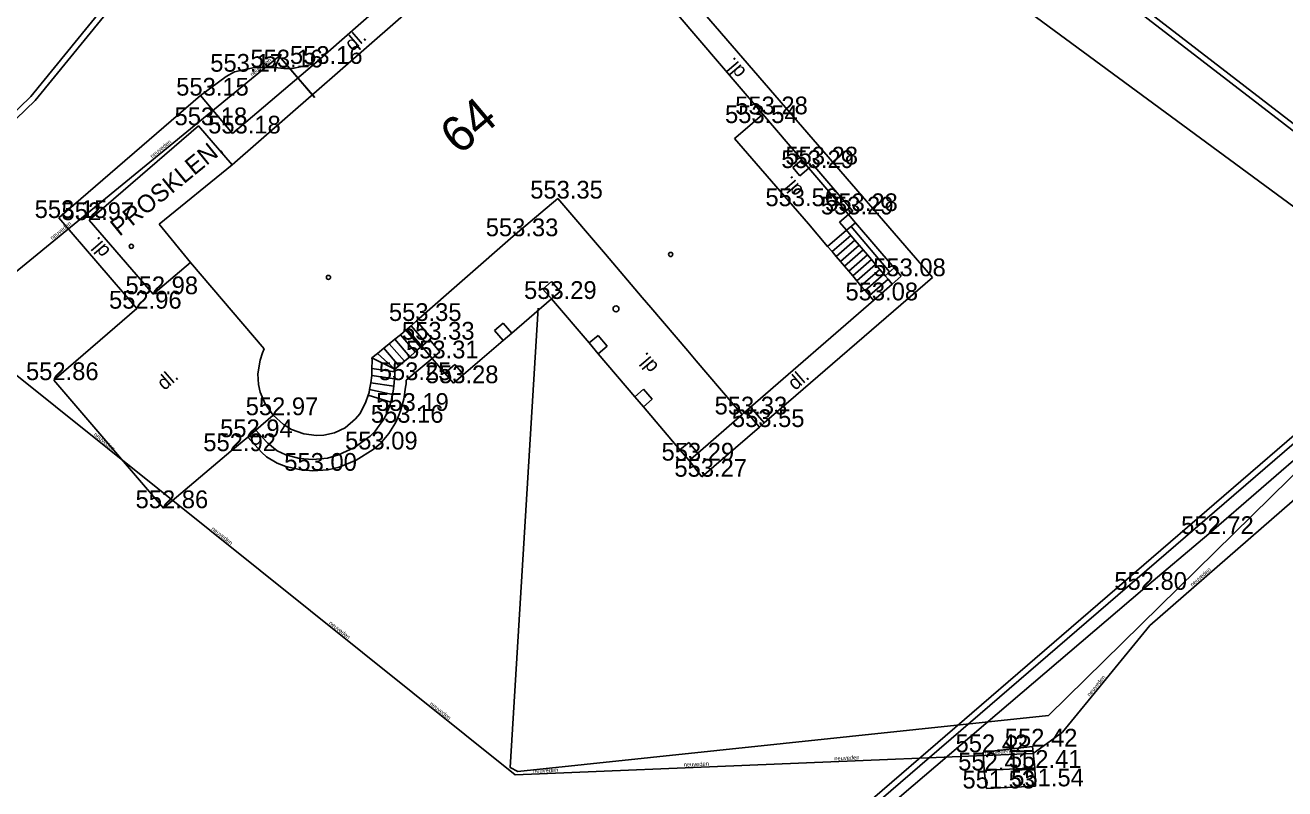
# Model space of a CAD drawing. Extents: x -669995 to -669686, y -1125551 to -1125263.
# Drawn here: x -669941 to -669887.8, y -1125457 to -1125424.8 of the extents above; entities that cross this region are included whole.
import ezdxf

# ---------------------------------------------------------------- set-up
doc = ezdxf.new("R2010")
doc.units = 0
for name, color, linetype in [('G_Bod_tecka', 7, 'Continuous'), ('G_Bod_vyska', 7, 'Continuous'), ('G_Budovy-znacky', 7, 'Continuous'), ('G_Budovy_Objekty', 7, 'Continuous'), ('G_Budovy_vstupy', 7, 'Continuous'), ('G_Cesty_Schody', 7, 'Continuous'), ('G_Cisla_popisna', 7, 'Continuous'), ('G_Plochy_zpevnene', 7, 'Continuous'), ('G_Ploty', 7, 'Continuous'), ('G_Popisy_povrchu', 7, 'Continuous'), ('G_Poznamky_odkaz', 7, 'Continuous'), ('G_Z_KANAL_podz_kotovane', 7, 'Continuous'), ('G_Z_SPOJE_podz_geodeticky', 7, 'Continuous'), ('G_Z_SPOJE_podz_kotovane', 7, 'Continuous'), ('G_Z_SPOJE_podz_priblizne', 7, 'Continuous'), ('G_Zabradli_Svodidla', 7, 'Continuous'), ('Vrstva 13', 7, 'Continuous'), ('Vrstva 3', 7, 'Continuous')]:
    doc.layers.add(name, color=color, linetype=linetype)

msp = doc.modelspace()

# ---------------------------------------------------------------- linework, layer by layer
at = {"layer": 'G_Bod_tecka'}
for p, q in [((-669930.42, -1125426.54), (-669930.42, -1125426.54)), ((-669928.75, -1125426.39), (-669928.75, -1125426.39)), ((-669932.13, -1125426.72), (-669932.13, -1125426.72)), ((-669933.57, -1125427.73), (-669933.57, -1125427.73)), ((-669909.81, -1125428.52), (-669909.81, -1125428.52)), ((-669933.64, -1125428.98), (-669933.64, -1125428.98)), ((-669910.24, -1125428.89), (-669910.24, -1125428.89)), ((-669932.22, -1125429.33), (-669932.22, -1125429.33)), ((-669907.86, -1125430.79), (-669907.86, -1125430.79)), ((-669907.69, -1125430.64), (-669907.69, -1125430.64)), ((-669918.47, -1125432.08), (-669918.47, -1125432.08)), ((-669908.52, -1125432.4), (-669908.52, -1125432.4)), ((-669939.55, -1125432.9), (-669939.55, -1125432.9)), ((-669938.27, -1125432.99), (-669938.27, -1125432.99)), ((-669906.19, -1125432.75), (-669906.19, -1125432.75)), ((-669906.01, -1125432.61), (-669906.01, -1125432.61)), ((-669920.35, -1125433.67), (-669920.35, -1125433.67)), ((-669903.96, -1125435.36), (-669903.96, -1125435.36)), ((-669935.57, -1125436.12), (-669935.57, -1125436.12)), ((-669918.73, -1125436.32), (-669918.73, -1125436.32)), ((-669905.13, -1125436.38), (-669905.13, -1125436.38)), ((-669936.25, -1125436.73), (-669936.25, -1125436.73)), ((-669924.44, -1125437.25), (-669924.44, -1125437.25)), ((-669923.89, -1125438.04), (-669923.89, -1125438.04)), ((-669923.78, -1125438.83), (-669923.78, -1125438.83)), ((-669939.76, -1125439.75), (-669939.76, -1125439.75)), ((-669924.87, -1125439.75), (-669924.87, -1125439.75)), ((-669922.88, -1125439.88), (-669922.88, -1125439.88)), ((-669930.49, -1125441.23), (-669930.49, -1125441.23)), ((-669925.12, -1125441.05), (-669925.12, -1125441.05)), ((-669910.68, -1125441.2), (-669910.68, -1125441.2)), ((-669925.33, -1125441.55), (-669925.33, -1125441.55)), ((-669909.95, -1125441.73), (-669909.95, -1125441.73)), ((-669931.57, -1125442.16), (-669931.57, -1125442.16)), ((-669932.28, -1125442.75), (-669932.28, -1125442.75)), ((-669926.27, -1125442.68), (-669926.27, -1125442.68)), ((-669928.82, -1125443.58), (-669928.82, -1125443.58)), ((-669912.92, -1125443.15), (-669912.92, -1125443.15)), ((-669912.38, -1125443.83), (-669912.38, -1125443.83)), ((-669935.13, -1125445.16), (-669935.13, -1125445.16)), ((-669890.97, -1125446.25), (-669890.97, -1125446.25)), ((-669893.77, -1125448.61), (-669893.77, -1125448.61)), ((-669898.42, -1125455.23), (-669898.42, -1125455.23)), ((-669900.5, -1125455.47), (-669900.5, -1125455.47)), ((-669900.45, -1125456.24), (-669900.45, -1125456.24)), ((-669898.31, -1125456.13), (-669898.31, -1125456.13)), ((-669898.29, -1125456.91), (-669898.29, -1125456.91)), ((-669900.35, -1125457), (-669900.35, -1125457))]:
    msp.add_line(p, q, dxfattribs=at)
at = {"layer": 'G_Budovy-znacky'}
for centre, radius in [((-669936.49, -1125434.1), 0.0875), ((-669913.7, -1125434.44), 0.0875), ((-669928.16, -1125435.41), 0.0875), ((-669916.01, -1125436.74), 0.125)]:
    msp.add_circle(centre, radius, dxfattribs=at)
at = {"layer": 'G_Budovy_Objekty'}
for p, q in [((-669921.89, -1125421.62), (-669932.23, -1125430.65)), ((-669913.39, -1125424.33), (-669909.81, -1125428.52)), ((-669909.81, -1125428.52), (-669910.24, -1125428.89)), ((-669909.81, -1125428.52), (-669908.16, -1125430.44)), ((-669933.65, -1125429.01), (-669938.27, -1125432.99)), ((-669932.23, -1125430.65), (-669933.65, -1125429.01)), ((-669910.95, -1125429.5), (-669911, -1125429.54)), ((-669911, -1125429.54), (-669908.52, -1125432.4)), ((-669932.23, -1125430.65), (-669935.31, -1125433.16)), ((-669908.54, -1125430.76), (-669908.16, -1125430.44)), ((-669908.54, -1125430.76), (-669908.24, -1125431.12)), ((-669908.24, -1125431.12), (-669907.86, -1125430.79)), ((-669908.16, -1125430.44), (-669907.86, -1125430.79)), ((-669907.86, -1125430.79), (-669906.19, -1125432.75)), ((-669918.47, -1125432.08), (-669916.46, -1125434.43)), ((-669935.57, -1125436.12), (-669938.27, -1125432.99)), ((-669906.57, -1125433.08), (-669906.19, -1125432.75)), ((-669906.19, -1125432.75), (-669905.89, -1125433.1)), ((-669935.31, -1125433.16), (-669933.99, -1125434.78)), ((-669907.88, -1125433.15), (-669907.07, -1125434.11)), ((-669907.07, -1125434.11), (-669906.27, -1125433.42)), ((-669906.57, -1125433.08), (-669906.27, -1125433.42)), ((-669906.27, -1125433.42), (-669905.89, -1125433.1)), ((-669906.27, -1125433.42), (-669906.09, -1125433.64)), ((-669905.89, -1125433.1), (-669904.26, -1125435.01)), ((-669924.44, -1125437.25), (-669920.35, -1125433.67)), ((-669906.09, -1125433.64), (-669905.92, -1125433.84)), ((-669905.92, -1125433.84), (-669905.74, -1125434.05)), ((-669905.74, -1125434.05), (-669905.57, -1125434.25)), ((-669907.07, -1125434.11), (-669906.88, -1125434.32)), ((-669906.88, -1125434.32), (-669906.71, -1125434.53)), ((-669906.71, -1125434.53), (-669906.53, -1125434.74)), ((-669905.57, -1125434.25), (-669905.39, -1125434.46)), ((-669905.39, -1125434.46), (-669905.22, -1125434.66)), ((-669933.99, -1125434.78), (-669935.57, -1125436.12)), ((-669933.99, -1125434.78), (-669930.88, -1125438.43)), ((-669906.53, -1125434.74), (-669906.36, -1125434.94)), ((-669906.36, -1125434.94), (-669906.18, -1125435.15)), ((-669905.22, -1125434.66), (-669905.04, -1125434.87)), ((-669905.04, -1125434.87), (-669904.87, -1125435.08)), ((-669904.87, -1125435.08), (-669904.69, -1125435.28)), ((-669904.64, -1125435.34), (-669904.26, -1125435.01)), ((-669904.26, -1125435.01), (-669903.96, -1125435.36)), ((-669918.73, -1125435.58), (-669919.1, -1125435.9)), ((-669918.37, -1125436.01), (-669918.73, -1125435.58)), ((-669906.18, -1125435.15), (-669906.01, -1125435.35)), ((-669906.01, -1125435.35), (-669905.83, -1125435.56)), ((-669905.83, -1125435.56), (-669905.66, -1125435.76)), ((-669904.69, -1125435.28), (-669904.64, -1125435.34)), ((-669904.64, -1125435.34), (-669904.51, -1125435.49)), ((-669904.51, -1125435.49), (-669904.34, -1125435.69)), ((-669903.96, -1125435.36), (-669904.34, -1125435.69)), ((-669919.1, -1125435.9), (-669918.73, -1125436.32)), ((-669918.37, -1125436.01), (-669918.73, -1125436.32)), ((-669905.66, -1125435.76), (-669905.48, -1125435.97)), ((-669905.48, -1125435.97), (-669905.3, -1125436.17)), ((-669905.3, -1125436.17), (-669905.13, -1125436.38)), ((-669904.34, -1125435.69), (-669905.13, -1125436.38)), ((-669918.73, -1125436.32), (-669920.41, -1125437.76)), ((-669917.15, -1125438.18), (-669918.73, -1125436.32)), ((-669914.9, -1125436.26), (-669914.54, -1125436.68)), ((-669905.13, -1125436.38), (-669910.33, -1125440.89)), ((-669924.67, -1125437.45), (-669924.44, -1125437.25)), ((-669924.89, -1125437.64), (-669925.12, -1125437.83)), ((-669924.84, -1125437.6), (-669924.89, -1125437.64)), ((-669924.84, -1125437.6), (-669924.67, -1125437.45)), ((-669924.84, -1125437.6), (-669924.22, -1125438.32)), ((-669920.78, -1125437.34), (-669921.14, -1125437.65)), ((-669921.14, -1125437.65), (-669920.78, -1125438.08)), ((-669920.78, -1125437.34), (-669920.41, -1125437.76)), ((-669920.41, -1125437.76), (-669920.78, -1125438.08)), ((-669925.59, -1125438.21), (-669925.82, -1125438.4)), ((-669925.36, -1125438.02), (-669925.59, -1125438.21)), ((-669925.12, -1125437.83), (-669925.36, -1125438.02)), ((-669920.78, -1125438.08), (-669922.46, -1125439.51)), ((-669916.77, -1125437.86), (-669917.15, -1125438.18)), ((-669917.15, -1125438.18), (-669916.76, -1125438.64)), ((-669916.38, -1125438.32), (-669916.77, -1125437.86)), ((-669926.08, -1125438.62), (-669926.32, -1125438.81)), ((-669925.82, -1125438.4), (-669926.08, -1125438.62)), ((-669924.22, -1125438.32), (-669923.78, -1125438.83)), ((-669923.78, -1125438.83), (-669923.24, -1125439.46)), ((-669916.38, -1125438.32), (-669916.76, -1125438.64)), ((-669915.22, -1125440.45), (-669916.76, -1125438.64)), ((-669912.98, -1125438.51), (-669912.62, -1125438.93)), ((-669926.32, -1125439.56), (-669926.32, -1125439.26)), ((-669922.82, -1125439.09), (-669923.24, -1125439.46)), ((-669922.82, -1125439.09), (-669922.46, -1125439.51)), ((-669926.42, -1125440.15), (-669926.37, -1125439.86)), ((-669926.37, -1125439.86), (-669926.32, -1125439.56)), ((-669923.24, -1125439.46), (-669922.88, -1125439.88)), ((-669922.46, -1125439.51), (-669922.88, -1125439.88)), ((-669914.85, -1125440.13), (-669915.22, -1125440.45)), ((-669914.48, -1125440.56), (-669914.85, -1125440.13)), ((-669914.85, -1125440.88), (-669915.22, -1125440.45)), ((-669914.48, -1125440.56), (-669914.85, -1125440.88)), ((-669913.31, -1125442.69), (-669914.85, -1125440.88)), ((-669911.06, -1125440.76), (-669910.68, -1125441.2)), ((-669910.33, -1125440.89), (-669910.52, -1125441.06)), ((-669910.68, -1125441.2), (-669912.55, -1125442.83)), ((-669910.52, -1125441.06), (-669910.68, -1125441.2)), ((-669912.94, -1125442.38), (-669913.31, -1125442.69)), ((-669912.55, -1125442.83), (-669912.94, -1125442.38)), ((-669912.92, -1125443.15), (-669913.31, -1125442.69)), ((-669912.55, -1125442.83), (-669912.92, -1125443.15)), ((-669898.42, -1125455.23), (-669900.5, -1125455.47)), ((-669898.31, -1125456.13), (-669898.42, -1125455.23)), ((-669900.5, -1125455.47), (-669900.45, -1125456.24)), ((-669898.31, -1125456.13), (-669900.45, -1125456.24)), ((-669900.45, -1125456.24), (-669900.35, -1125457)), ((-669898.29, -1125456.91), (-669898.31, -1125456.13)), ((-669900.35, -1125457), (-669898.29, -1125456.91))]:
    msp.add_line(p, q, dxfattribs=at)
for points in [[(-669930.88, -1125438.43), (-669930.95, -1125438.59), (-669931.05, -1125438.91), (-669931.14, -1125439.48), (-669931.12, -1125439.93), (-669931.04, -1125440.26), (-669930.83, -1125440.75), (-669930.49, -1125441.23), (-669930.06, -1125441.63), (-669929.72, -1125441.83), (-669929.2, -1125442.02), (-669928.66, -1125442.09), (-669928.36, -1125442.08), (-669927.9, -1125441.98), (-669927.46, -1125441.76), (-669927.02, -1125441.39), (-669926.84, -1125441.18), (-669926.7, -1125440.94), (-669926.58, -1125440.67), (-669926.48, -1125440.39), (-669926.44, -1125440.27), (-669926.42, -1125440.15)], [(-669926.32, -1125439.26), (-669926.31, -1125438.92), (-669926.32, -1125438.81)]]:
    msp.add_lwpolyline(points, dxfattribs=at)
at = {"layer": 'G_Budovy_vstupy'}
for p, q in [((-669910.95, -1125429.5), (-669910.24, -1125428.89)), ((-669920.35, -1125433.67), (-669918.47, -1125432.08)), ((-669907.88, -1125433.15), (-669908.52, -1125432.4)), ((-669916.46, -1125434.43), (-669914.9, -1125436.26)), ((-669914.54, -1125436.68), (-669912.98, -1125438.51)), ((-669912.62, -1125438.93), (-669911.06, -1125440.76))]:
    msp.add_line(p, q, dxfattribs=at)
at = {"layer": 'G_Cesty_Schody'}
for p, q in [((-669907.69, -1125430.64), (-669907.86, -1125430.79)), ((-669907.69, -1125430.64), (-669906.01, -1125432.61)), ((-669906.01, -1125432.61), (-669906.19, -1125432.75)), ((-669906.09, -1125433.64), (-669906.88, -1125434.32)), ((-669905.92, -1125433.84), (-669906.71, -1125434.53)), ((-669905.74, -1125434.05), (-669906.53, -1125434.74)), ((-669905.57, -1125434.25), (-669906.36, -1125434.94)), ((-669905.39, -1125434.46), (-669906.18, -1125435.15)), ((-669905.22, -1125434.66), (-669906.01, -1125435.35)), ((-669905.04, -1125434.87), (-669905.83, -1125435.56)), ((-669904.87, -1125435.08), (-669905.66, -1125435.76)), ((-669904.69, -1125435.28), (-669905.48, -1125435.97)), ((-669904.51, -1125435.49), (-669905.3, -1125436.17)), ((-669923.81, -1125437.98), (-669924.44, -1125437.25)), ((-669924.27, -1125438.36), (-669924.89, -1125437.64)), ((-669924.04, -1125438.17), (-669924.67, -1125437.45)), ((-669924.95, -1125438.95), (-669925.59, -1125438.21)), ((-669924.72, -1125438.76), (-669925.36, -1125438.02)), ((-669924.5, -1125438.56), (-669925.12, -1125437.83)), ((-669923.81, -1125437.98), (-669923.89, -1125438.04)), ((-669925.35, -1125439.29), (-669926.32, -1125438.81)), ((-669925.35, -1125439.29), (-669926.08, -1125438.62)), ((-669925.18, -1125439.14), (-669925.82, -1125438.4)), ((-669925.35, -1125439.4), (-669926.32, -1125439.26)), ((-669925.4, -1125440), (-669926.37, -1125439.86)), ((-669925.37, -1125439.7), (-669926.32, -1125439.56)), ((-669925.53, -1125440.68), (-669926.48, -1125440.39)), ((-669925.46, -1125440.36), (-669926.42, -1125440.15)), ((-669910.33, -1125440.89), (-669909.75, -1125441.56)), ((-669930.49, -1125441.23), (-669931.23, -1125441.87)), ((-669910.52, -1125441.06), (-669909.95, -1125441.73))]:
    msp.add_line(p, q, dxfattribs=at)
msp.add_lwpolyline([(-669928.75, -1125426.39), (-669929.21, -1125426.48), (-669929.68, -1125426.58), (-669930.05, -1125426.58), (-669930.42, -1125426.54), (-669931.28, -1125426.54), (-669932.13, -1125426.72), (-669932.48, -1125426.92), (-669932.8, -1125427.16), (-669933.19, -1125427.44), (-669933.57, -1125427.73)], dxfattribs=at)
at = {"layer": 'G_Plochy_zpevnene'}
for p, q in [((-669923.74, -1125421.98), (-669928.75, -1125426.39)), ((-669912.72, -1125423.75), (-669902.64, -1125435.41)), ((-669928.75, -1125426.39), (-669932.22, -1125429.33)), ((-669933.57, -1125427.73), (-669939.55, -1125432.9)), ((-669932.22, -1125429.33), (-669933.57, -1125427.73)), ((-669939.55, -1125432.9), (-669936.25, -1125436.73)), ((-669902.64, -1125435.41), (-669909.75, -1125441.56)), ((-669890.97, -1125446.25), (-669878.91, -1125435.78)), ((-669936.25, -1125436.73), (-669939.76, -1125439.75)), ((-669939.76, -1125439.75), (-669935.13, -1125445.16)), ((-669909.95, -1125441.73), (-669912.38, -1125443.83)), ((-669909.75, -1125441.56), (-669909.95, -1125441.73)), ((-669932.28, -1125442.75), (-669931.57, -1125442.16)), ((-669935.13, -1125445.16), (-669932.28, -1125442.75)), ((-669912.38, -1125443.83), (-669912.92, -1125443.15)), ((-669893.77, -1125448.61), (-669890.97, -1125446.25)), ((-669904.51, -1125457.78), (-669893.77, -1125448.61))]:
    msp.add_line(p, q, dxfattribs=at)
at = {"layer": 'G_Ploty'}
for p, q in [((-669940.74, -1125427.77), (-669920.7, -1125403.21)), ((-669940.55, -1125427.93), (-669920.66, -1125403.56)), ((-669879.12, -1125435.3), (-669920.7, -1125403.21)), ((-669920.66, -1125403.56), (-669879.52, -1125435.31)), ((-669940.74, -1125427.77), (-669966.22, -1125452.38)), ((-669965.88, -1125452.4), (-669940.55, -1125427.93)), ((-669879.52, -1125435.31), (-669905.49, -1125457.7)), ((-669905.22, -1125457.8), (-669879.31, -1125435.47)), ((-669924.22, -1125438.32), (-669924.04, -1125438.17)), ((-669924.04, -1125438.17), (-669923.89, -1125438.04)), ((-669923.45, -1125438.55), (-669923.89, -1125438.04)), ((-669924.95, -1125438.95), (-669924.72, -1125438.76)), ((-669924.87, -1125439.75), (-669923.78, -1125438.83)), ((-669924.72, -1125438.76), (-669924.5, -1125438.56)), ((-669924.5, -1125438.56), (-669924.27, -1125438.36)), ((-669924.27, -1125438.36), (-669924.22, -1125438.32)), ((-669923.78, -1125438.83), (-669923.45, -1125438.55)), ((-669925.35, -1125439.29), (-669925.18, -1125439.14)), ((-669925.35, -1125439.4), (-669925.35, -1125439.29)), ((-669925.18, -1125439.14), (-669924.95, -1125438.95)), ((-669925.4, -1125440), (-669925.37, -1125439.7)), ((-669925.53, -1125440.68), (-669925.46, -1125440.36)), ((-669931.57, -1125442.16), (-669931.23, -1125441.87))]:
    msp.add_line(p, q, dxfattribs=at)
for points in [[(-669931.57, -1125442.16), (-669931.27, -1125442.48), (-669930.98, -1125442.8), (-669930.77, -1125442.99), (-669930.32, -1125443.26), (-669929.96, -1125443.4), (-669929.38, -1125443.53), (-669928.82, -1125443.58), (-669928.18, -1125443.54), (-669927.7, -1125443.42), (-669926.99, -1125443.13), (-669926.27, -1125442.68), (-669925.96, -1125442.42), (-669925.61, -1125442.01), (-669925.33, -1125441.55), (-669925.21, -1125441.3), (-669925.12, -1125441.05), (-669924.98, -1125440.55), (-669924.9, -1125440.04), (-669924.88, -1125439.9), (-669924.87, -1125439.75)], [(-669925.37, -1125439.7), (-669925.36, -1125439.6), (-669925.35, -1125439.4)], [(-669925.46, -1125440.36), (-669925.42, -1125440.21), (-669925.4, -1125440)], [(-669931.23, -1125441.87), (-669930.98, -1125442.14), (-669930.72, -1125442.41), (-669930.32, -1125442.73), (-669929.96, -1125442.9), (-669929.38, -1125443.06), (-669928.82, -1125443.1), (-669928.2, -1125443.04), (-669927.74, -1125442.91), (-669927.06, -1125442.59), (-669926.39, -1125442.12), (-669926.18, -1125441.9), (-669926.01, -1125441.66), (-669925.85, -1125441.44), (-669925.72, -1125441.21), (-669925.57, -1125440.82), (-669925.53, -1125440.68)]]:
    msp.add_lwpolyline(points, dxfattribs=at)
at = {"layer": 'G_Z_KANAL_podz_kotovane'}
for points in [[(-669928.74, -1125427.81), (-669930.24, -1125426.07), (-669943.68, -1125437.06), (-669941.82, -1125439.16), (-669920.27, -1125456.43), (-669898.38, -1125455.52)], [(-669898.38, -1125455.52), (-669897.15, -1125454.62), (-669893.45, -1125450.11), (-669885.03, -1125442.78), (-669884.87, -1125442.37)]]:
    msp.add_lwpolyline(points, dxfattribs=at)
at = {"layer": 'G_Z_SPOJE_podz_geodeticky'}
for points in [[(-669882.04, -1125353.23), (-669888.47, -1125362.55), (-669902.63, -1125378.37), (-669910.95, -1125386.95), (-669915.3, -1125391.93), (-669919.2, -1125397.1), (-669925.01, -1125405.29), (-669926.3, -1125407.53), (-669926.15, -1125411.27), (-669924.02, -1125413.38), (-669921.22, -1125413.87), (-669913.82, -1125412.99), (-669911.46, -1125414.56), (-669901.71, -1125421.87), (-669885.88, -1125433.52)], [(-669919.3, -1125436.71), (-669920.48, -1125456.12), (-669920.16, -1125456.28), (-669897.74, -1125453.92), (-669885.22, -1125441.62), (-669884.53, -1125441.6), (-669868.9, -1125450.43)]]:
    msp.add_lwpolyline(points, dxfattribs=at)
at = {"layer": 'G_Z_SPOJE_podz_kotovane'}
msp.add_lwpolyline([(-669919.3, -1125436.71), (-669920.48, -1125456.12), (-669920.16, -1125456.28), (-669897.74, -1125453.92), (-669885.22, -1125441.62), (-669884.53, -1125441.6), (-669868.9, -1125450.43)], dxfattribs=at)
at = {"layer": 'G_Z_SPOJE_podz_priblizne'}
msp.add_lwpolyline([(-669919.3, -1125436.71), (-669920.48, -1125456.12), (-669920.16, -1125456.28), (-669897.74, -1125453.92), (-669885.22, -1125441.62), (-669884.53, -1125441.6), (-669868.9, -1125450.43)], dxfattribs=at)
at = {"layer": 'G_Zabradli_Svodidla'}
msp.add_line((-669906.08, -1125433.26), (-669904.45, -1125435.17), dxfattribs=at)
at = {"layer": 'Vrstva 13'}
for points in [[(-669928.742, -1125427.808), (-669930.244, -1125426.067), (-669943.68, -1125437.06), (-669941.82, -1125439.16), (-669920.27, -1125456.43), (-669898.384, -1125455.525)], [(-669898.384, -1125455.525), (-669897.15, -1125454.62), (-669893.45, -1125450.11), (-669885.03, -1125442.78), (-669884.87, -1125442.37)]]:
    msp.add_lwpolyline(points, dxfattribs=at)

# ---------------------------------------------------------------- texts
at = {"layer": 'G_Bod_vyska'}
for s, p in [('553.17', (-669933.152, -1125426.72)), ('553.16', (-669931.456, -1125426.54)), ('553.16', (-669929.786, -1125426.39)), ('553.15', (-669934.592, -1125427.73)), ('553.54', (-669911.404, -1125428.89)), ('553.28', (-669910.974, -1125428.52)), ('553.18', (-669934.662, -1125428.98)), ('553.18', (-669933.242, -1125429.33)), ('553.29', (-669909.026, -1125430.79)), ('553.28', (-669908.854, -1125430.64)), ('553.35', (-669919.634, -1125432.08)), ('553.56', (-669909.698, -1125432.4)), ('553.28', (-669907.174, -1125432.61)), ('553.15', (-669940.572, -1125432.9)), ('552.97', (-669939.436, -1125432.99)), ('553.29', (-669907.356, -1125432.75)), ('553.33', (-669921.514, -1125433.67)), ('553.08', (-669905.146, -1125435.36)), ('552.98', (-669936.736, -1125436.12)), ('553.29', (-669919.896, -1125436.32)), ('553.08', (-669906.316, -1125436.38)), ('552.96', (-669937.43, -1125436.73)), ('553.35', (-669925.604, -1125437.25)), ('553.33', (-669925.054, -1125438.04)), ('553.31', (-669924.882, -1125438.83)), ('552.86', (-669940.938, -1125439.75)), ('553.25', (-669926.034, -1125439.75)), ('553.28', (-669924.044, -1125439.88)), ('553.19', (-669926.144, -1125441.05)), ('553.33', (-669911.844, -1125441.2)), ('552.97', (-669931.656, -1125441.23)), ('553.16', (-669926.366, -1125441.55)), ('553.55', (-669911.114, -1125441.73)), ('552.94', (-669932.736, -1125442.16)), ('552.92', (-669933.446, -1125442.75)), ('553.09', (-669927.458, -1125442.68)), ('553.29', (-669914.086, -1125443.15)), ('553.00', (-669930.027, -1125443.58)), ('553.27', (-669913.544, -1125443.83)), ('552.86', (-669936.308, -1125445.16)), ('552.72', (-669892.134, -1125446.25)), ('552.80', (-669894.956, -1125448.61)), ('552.42', (-669901.664, -1125455.47)), ('552.42', (-669899.584, -1125455.23)), ('552.41', (-669901.552, -1125456.24)), ('552.41', (-669899.412, -1125456.13)), ('551.53', (-669901.372, -1125457)), ('551.54', (-669899.312, -1125456.91))]:
    msp.add_text(s, height=0.75, dxfattribs=at).set_placement(p)
at = {"layer": 'G_Cisla_popisna'}
msp.add_text('64', height=1.5, rotation=40.2227, dxfattribs=at).set_placement((-669922.63, -1125430.276))
at = {"layer": 'G_Popisy_povrchu'}
for rotation, p in [(40.8166, (-669927.148, -1125425.881)), (130.442, (-669910.493, -1125426.702)), (130.442, (-669908.073, -1125431.712)), (130.442, (-669937.353, -1125434.282)), (130.442, (-669914.193, -1125439.162)), (40.8166, (-669935.088, -1125440.211)), (40.8166, (-669908.438, -1125440.211))]:
    msp.add_text('dl.', height=0.6, rotation=rotation, dxfattribs=at).set_placement(p)
at = {"layer": 'G_Poznamky_odkaz'}
msp.add_text('PROSKLEN.', height=0.75, rotation=39.1769, dxfattribs=at).set_placement((-669936.989, -1125433.699))
at = {"layer": 'Vrstva 3'}
for rotation, p in [(39.2317, (-669931.381, -1125426.928)), (39.2585, (-669935.605, -1125430.386)), (39.277, (-669939.828, -1125433.84)), (321.3036, (-669938.094, -1125442.079)), (321.2625, (-669933.125, -1125446.061)), (41.0043, (-669891.659, -1125448.481)), (321.267, (-669928.157, -1125450.041)), (50.6406, (-669895.994, -1125453.128)), (321.267, (-669923.898, -1125453.455)), (2.3725, (-669900.424, -1125455.557)), (2.4018, (-669913.146, -1125456.082)), (2.3713, (-669906.785, -1125455.819)), (2.3713, (-669919.507, -1125456.345))]:
    msp.add_text('neuveden', height=0.1755, rotation=rotation, dxfattribs=at).set_placement(p)

doc.saveas('drawing.dxf')
